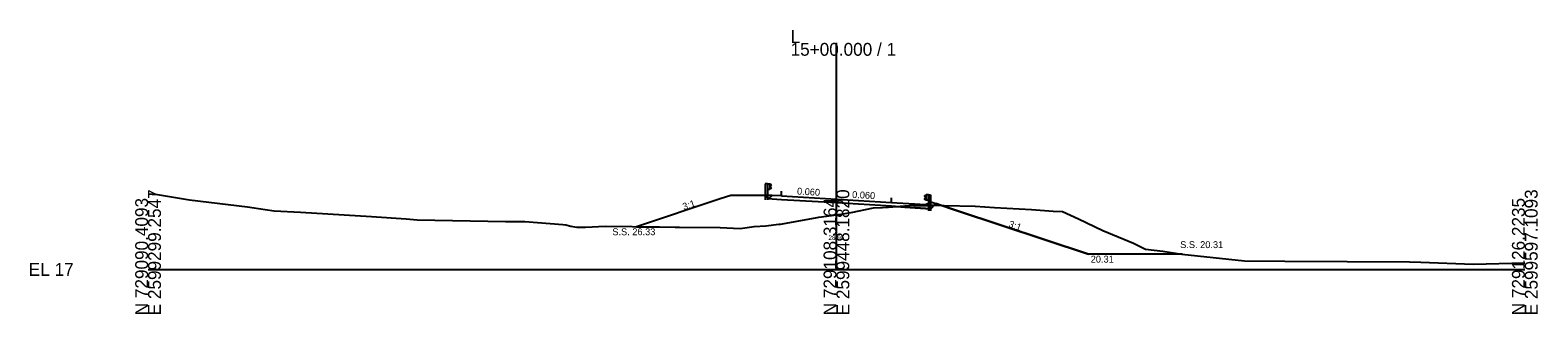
# Model space of a CAD drawing. Extents: x -26 to 3303, y -10 to 9555.
# Drawn here: x 974.3 to 1302.8, y -9.7 to 52.2 of the extents above; entities that cross this region are included whole.
import ezdxf

# ---------------------------------------------------------------- set-up
doc = ezdxf.new("R2010")
doc.units = 0
for name, color, linetype in [('Exist Cross Section Cell', 7, 'Continuous'), ('Exist XS Center Line Elevation Label', 7, 'Continuous'), ('Exist XS Ground Line', 7, 'Continuous'), ('Prop XS Ditch Slope Text', 7, 'Continuous'), ('Prop XS Ditch Standard Text', 7, 'Continuous'), ('Prop XS Dump Level', 7, 'Continuous'), ('Prop XS Earthwork Shape', 7, 'Continuous'), ('Prop XS EOT Tick Mark', 7, 'Continuous'), ('Prop XS Finish Grade', 7, 'Continuous'), ('Prop XS Finish Grade Earthwork', 7, 'Continuous'), ('Prop XS Finish Grade Paved Shoulder', 7, 'Continuous'), ('Prop XS Finish Grade Pavement', 7, 'Continuous'), ('Prop XS Pvmt Edge Slope', 7, 'Continuous'), ('Prop XS SE Text', 7, 'Continuous'), ('Prop XS Side Slope Text', 7, 'Continuous'), ('Prop XS SS Elevation Text', 7, 'Continuous'), ('Prop XS Subgrade Earthwork', 7, 'Continuous'), ('Typical Curb CELL', 7, 'Continuous'), ('Typical Guardrail CELL', 7, 'Continuous')]:
    doc.layers.add(name, color=color, linetype=linetype)

msp = doc.modelspace()

# ---------------------------------------------------------------- linework, layer by layer
at = {"layer": 'Exist Cross Section Cell'}
for p, q in [((1150, 0), (1150, 49.44)), ((1000, 0), (1150, 0)), ((1150, 0), (1300, 0))]:
    msp.add_line(p, q, dxfattribs=at)
at = {"layer": 'Exist XS Ground Line'}
msp.add_lwpolyline([(1000, 16.48), (1000.87, 16.42), (1002.07, 16.35), (1009.06, 15.23), (1021.67, 13.68), (1025.49, 13.1), (1027.5, 12.82), (1033.25, 12.54), (1048.67, 11.57), (1056.23, 11.08), (1058.66, 10.86), (1077.86, 10.49), (1082.12, 10.5), (1090.37, 9.83), (1091.05, 9.76), (1092.09, 9.45), (1093.45, 9.2), (1095.34, 9.2), (1099.6, 9.42), (1111.46, 9.27), (1114.83, 9.26), (1115.82, 9.26), (1124.67, 9.19), (1129.05, 8.95), (1132.04, 9.39), (1134.6, 9.53), (1137.43, 9.86), (1137.82, 9.9), (1145.46, 11.25), (1146.2, 11.39), (1150, 11.95), (1153.19, 12.42), (1158.09, 13.42), (1160.03, 13.56), (1160.74, 13.58), (1161.31, 13.62), (1167.99, 14.12), (1173.51, 13.97), (1180.22, 13.79), (1184.46, 13.49), (1192.47, 13.06), (1197.22, 12.74), (1199.27, 12.62), (1202.71, 11.05), (1208.08, 8.47), (1214.71, 5.73), (1217.36, 4.44), (1221.12, 3.98), (1225.29, 3.31), (1238.9, 1.85), (1247.73, 1.82), (1274.85, 1.67), (1277.35, 1.58), (1288.74, 1.13), (1300, 1.48)], dxfattribs=at)
at = {"layer": 'Prop XS Dump Level'}
for p, q in [((1138, 16.06), (1150, 15.34)), ((1150, 15.34), (1162, 14.62))]:
    msp.add_line(p, q, dxfattribs=at)
at = {"layer": 'Prop XS Earthwork Shape'}
for points in [[(1160.03, 13.56), (1160.74, 13.58), (1161.31, 13.62), (1162.85, 13.74), (1162, 13.79), (1150, 14.51), (1138, 15.23), (1136, 15.35), (1135.21, 15.39), (1134.43, 16.18), (1127, 16.18), (1124.64, 15.39), (1106.46, 9.33), (1111.46, 9.27), (1114.83, 9.26), (1115.82, 9.26), (1124.67, 9.19), (1129.05, 8.95), (1132.04, 9.39), (1134.6, 9.53), (1137.43, 9.86), (1137.82, 9.9), (1145.46, 11.25), (1146.2, 11.39), (1150, 11.95), (1153.19, 12.42), (1158.09, 13.42)], [(1150, 14.51), (1138, 15.23), (1136, 15.35), (1135.21, 15.39), (1134.43, 16.18), (1127, 16.18), (1124.64, 15.39), (1106.46, 9.33), (1111.46, 9.27), (1114.83, 9.26), (1115.82, 9.26), (1124.67, 9.19), (1129.05, 8.95), (1132.04, 9.39), (1134.6, 9.53), (1137.43, 9.86), (1137.82, 9.9), (1145.46, 11.25), (1146.2, 11.39), (1150, 11.95), (1153.19, 12.42), (1158.09, 13.42), (1160.03, 13.56), (1160.74, 13.58), (1161.31, 13.62), (1162.85, 13.74), (1162, 13.79)], [(1162.85, 13.74), (1167.99, 14.12), (1171.32, 14.03), (1170.56, 13.27), (1164.89, 13.61), (1164, 13.67)], [(1162.85, 13.74), (1167.99, 14.12), (1171.32, 14.03), (1170.56, 13.27), (1164.89, 13.61), (1164, 13.67)], [(1171.32, 14.03), (1172.87, 13.99), (1171.68, 14.39)], [(1171.32, 14.03), (1172.87, 13.99), (1171.68, 14.39)], [(1172.87, 13.99), (1173.51, 13.97), (1180.22, 13.79), (1184.46, 13.49), (1192.47, 13.06), (1197.22, 12.74), (1199.27, 12.62), (1202.71, 11.05), (1208.08, 8.47), (1214.71, 5.73), (1217.36, 4.44), (1221.12, 3.98), (1225.29, 3.31), (1225.31, 3.31), (1204.91, 3.31), (1176.4, 12.81)], [(1172.87, 13.99), (1173.51, 13.97), (1180.22, 13.79), (1184.46, 13.49), (1192.47, 13.06), (1197.22, 12.74), (1199.27, 12.62), (1202.71, 11.05), (1208.08, 8.47), (1214.71, 5.73), (1217.36, 4.44), (1221.12, 3.98), (1225.29, 3.31), (1225.31, 3.31), (1204.91, 3.31), (1176.4, 12.81)]]:
    msp.add_lwpolyline(points, close=True, dxfattribs=at)
at = {"layer": 'Prop XS EOT Tick Mark'}
for p, q in [((1138, 16.06), (1138, 17.06)), ((1162, 14.62), (1162, 15.62))]:
    msp.add_line(p, q, dxfattribs=at)
at = {"layer": 'Prop XS Finish Grade'}
for p, q in [((1136, 16.18), (1134.43, 16.18)), ((1170.03, 14.5), (1170.56, 14.76)), ((1170.56, 14.76), (1171.68, 14.39))]:
    msp.add_line(p, q, dxfattribs=at)
at = {"layer": 'Prop XS Finish Grade Earthwork'}
for p, q in [((1124.64, 15.39), (1106.46, 9.33)), ((1127, 16.18), (1124.64, 15.39)), ((1134.43, 16.18), (1127, 16.18)), ((1171.68, 14.39), (1176.4, 12.81)), ((1176.4, 12.81), (1204.91, 3.31)), ((1225.31, 3.31), (1204.91, 3.31))]:
    msp.add_line(p, q, dxfattribs=at)
at = {"layer": 'Prop XS Finish Grade Paved Shoulder'}
for p, q in [((1138, 16.06), (1136, 16.18)), ((1162, 14.62), (1167, 14.32))]:
    msp.add_line(p, q, dxfattribs=at)
at = {"layer": 'Prop XS Finish Grade Pavement'}
for p, q in [((1138, 16.06), (1150, 15.34)), ((1150, 15.34), (1162, 14.62))]:
    msp.add_line(p, q, dxfattribs=at)
at = {"layer": 'Prop XS Pvmt Edge Slope'}
for p, q in [((1135.21, 15.39), (1134.43, 16.18)), ((1136, 16.18), (1135.21, 15.39)), ((1170.01, 13.83), (1170.56, 13.27)), ((1170.56, 13.27), (1171.68, 14.39))]:
    msp.add_line(p, q, dxfattribs=at)
at = {"layer": 'Prop XS Subgrade Earthwork'}
for p, q in [((1135.21, 15.39), (1134.43, 16.18)), ((1136, 15.35), (1135.21, 15.39)), ((1138, 15.23), (1136, 15.35)), ((1150, 14.51), (1138, 15.23)), ((1162, 13.79), (1150, 14.51)), ((1162, 13.79), (1164, 13.67)), ((1164, 13.67), (1164.89, 13.61)), ((1164.89, 13.61), (1170.56, 13.27)), ((1170.56, 13.27), (1171.68, 14.39))]:
    msp.add_line(p, q, dxfattribs=at)
at = {"layer": 'Typical Curb CELL'}
for p, q in [((1166.99, 13.9), (1167, 14.31)), ((1170.01, 13.83), (1166.99, 13.9)), ((1167, 14.32), (1167, 14.32)), ((1167.01, 14.32), (1169.33, 14.18)), ((1167.23, 14.05), (1167.32, 14.17)), ((1167.35, 14.05), (1167.23, 14.05)), ((1167.32, 14.17), (1167.35, 14.05)), ((1167.99, 13.98), (1168.06, 14.09)), ((1168.16, 14.01), (1167.99, 13.98)), ((1168.06, 14.09), (1168.16, 14.01)), ((1168.48, 14.02), (1168.57, 14.14)), ((1168.6, 14.02), (1168.48, 14.02)), ((1168.57, 14.14), (1168.6, 14.02)), ((1169.24, 13.95), (1169.31, 14.06)), ((1169.41, 13.98), (1169.24, 13.95)), ((1169.31, 14.06), (1169.41, 13.98)), ((1169.33, 14.18), (1170.03, 14.5)), ((1169.83, 14.18), (1169.84, 14.09)), ((1169.98, 14.13), (1169.83, 14.18)), ((1169.84, 14.09), (1169.98, 14.13)), ((1170.01, 13.83), (1170.03, 14.5))]:
    msp.add_line(p, q, dxfattribs=at)
for centre in [(1167.09, 14.14), (1167.13, 14.26), (1167.49, 14.18), (1167.55, 14), (1167.6, 13.97), (1167.64, 14.09), (1167.71, 14.09), (1167.76, 14.12), (1167.81, 14), (1168, 14.03), (1168.21, 14.01), (1168.23, 14.06), (1168.24, 14.12), (1168.29, 13.98), (1168.39, 14.02), (1168.48, 14.03), (1168.6, 13.97), (1168.8, 13.97), (1168.85, 13.93), (1168.89, 14.06), (1169.01, 14.09), (1169.06, 13.97), (1169.25, 14), (1169.28, 13.9), (1169.46, 13.98), (1169.48, 14.03), (1169.73, 14), (1169.85, 13.94), (1169.95, 14.21)]:
    msp.add_circle(centre, 0.00802, dxfattribs=at)
msp.add_arc((1167.01, 14.31), 0.0104, 86.5213, 178.5693, dxfattribs=at)
at = {"layer": 'Typical Guardrail CELL'}
for p, q in [((1135, 18.67), (1134.5, 18.67)), ((1134.5, 18.67), (1134.5, 16.18)), ((1135, 18.67), (1135, 16.18)), ((1135, 18.67), (1135.5, 18.67)), ((1135, 17.51), (1135.5, 17.51)), ((1135.5, 18.67), (1135.5, 17.51)), ((1135.5, 18.67), (1135.79, 18.46)), ((1135.5, 18.13), (1135.79, 18.34)), ((1135.5, 18.09), (1135.5, 18.13)), ((1135.5, 18.09), (1135.5, 18.04)), ((1135.5, 18.04), (1135.79, 17.84)), ((1135.5, 17.51), (1135.79, 17.71)), ((1135, 16.18), (1134.5, 16.18)), ((1134.5, 16.18), (1134.5, 15.17)), ((1135, 16.18), (1135, 15.17)), ((1169.53, 16.29), (1169.24, 16.08)), ((1169.53, 15.75), (1169.24, 15.96)), ((1169.53, 15.66), (1169.24, 15.46)), ((1169.53, 15.13), (1169.24, 15.33)), ((1170.03, 16.29), (1169.53, 16.29)), ((1169.53, 16.29), (1169.53, 15.13)), ((1169.53, 15.71), (1169.53, 15.75)), ((1169.53, 15.71), (1169.53, 15.66)), ((1170.03, 15.13), (1169.53, 15.13)), ((1170.03, 16.29), (1170.03, 13.8)), ((1170.03, 16.29), (1170.53, 16.29)), ((1170.03, 13.8), (1170.53, 13.8)), ((1170.03, 13.8), (1170.03, 12.79)), ((1170.53, 16.29), (1170.53, 13.8)), ((1170.53, 13.8), (1170.53, 12.79))]:
    msp.add_line(p, q, dxfattribs=at)
for centre, start, end in [((1135.74, 18.4), 304.9888, 54.997), ((1135.74, 17.77), 304.9634, 54.9941), ((1169.29, 16.02), 125.003, 235.0112), ((1169.29, 15.39), 125.0059, 235.0366)]:
    msp.add_arc(centre, 0.0776, start, end, dxfattribs=at)

# ---------------------------------------------------------------- texts
at = {"layer": 'Exist Cross Section Cell'}
for s, p in [('15+00.000 / 1', (1140, 46.64)), ('L', (1140, 49.44)), ('EL 17', (974, -1.4))]:
    msp.add_text(s, height=2.8, dxfattribs=at).set_placement(p)
for s, p in [('E 2599299.2547', (1002.8, -10)), ('E 2599448.1820', (1152.8, -10)), ('E 2599597.1093', (1302.8, -10)), ('N 729090.4093', (1000, -10)), ('N 729108.3164', (1150, -10)), ('N 729126.2235', (1300, -10))]:
    msp.add_text(s, height=2.8, rotation=90, dxfattribs=at).set_placement(p)
at = {"layer": 'Exist XS Center Line Elevation Label'}
msp.add_text('28.95', height=1, dxfattribs=at).set_placement((1148.27, 6.45))
at = {"layer": 'Prop XS Ditch Slope Text'}
msp.add_text('3:1', height=1.5, rotation=340.5558, dxfattribs=at).set_placement((1187.38, 9.33))
at = {"layer": 'Prop XS Ditch Standard Text'}
msp.add_text('20.31', height=1.5, dxfattribs=at).set_placement((1205.41, 1.5))
at = {"layer": 'Prop XS Dump Level'}
for s, height, p in [('Case1', 0.04, (1130, 16.14)), ('Eop', 0.3, (1167.99, 13.82)), ('Eop', 0.3, (1167.99, 13.82)), ('Case1', 0.04, (1170, 13.98)), ('Case1', 0.04, (1173, 13.74))]:
    msp.add_text(s, height=height, dxfattribs=at).set_placement(p)
at = {"layer": 'Prop XS SE Text'}
for p in [(1141.38, 16.36), (1153.38, 15.64)]:
    msp.add_text('0.060', height=1.5, rotation=356.5664, dxfattribs=at).set_placement(p)
at = {"layer": 'Prop XS Side Slope Text'}
msp.add_text('3:1', height=1.5, rotation=18.4349, dxfattribs=at).set_placement((1116.74, 12.93))
at = {"layer": 'Prop XS SS Elevation Text'}
for s, p in [('S.S. 26.33', (1101.17, 7.48)), ('S.S. 20.31', (1224.91, 4.67))]:
    msp.add_text(s, height=1.5, dxfattribs=at).set_placement(p)

doc.saveas('drawing.dxf')
